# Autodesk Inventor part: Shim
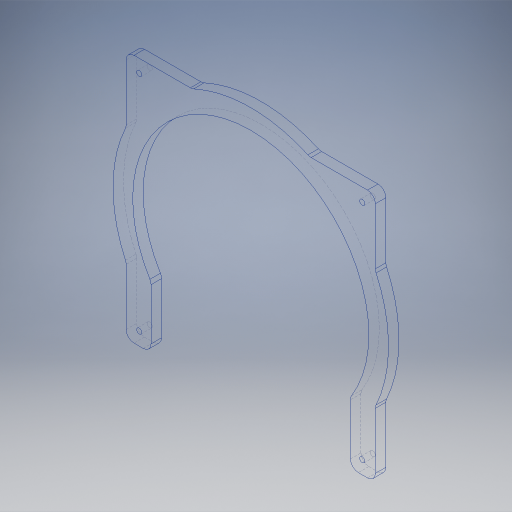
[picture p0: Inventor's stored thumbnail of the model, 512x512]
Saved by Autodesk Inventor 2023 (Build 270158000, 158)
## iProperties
Created: 2024-01
Part Number: Shim
Material: Aluminum 6061
Document SubType Name: Modeling
Designer: tornqvih
Density: 2.7 g/cm^3
Appearance: Aluminum - Flat
Mass: 32.8451 g
Surface Area: 76.8924 cm^2
Volume: 12.1649 cm^3
Author: tornqvih
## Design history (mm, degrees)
sketch "Sketch1"
  geometry: L1 (-47.5, -47.5)-(47.5, -47.5); L2 (47.5, -47.5)-(47.5, 47.5); L3 (47.5, 47.5)-(-47.5, 47.5); L4 (-47.5, 47.5)-(-47.5, -47.5); L5 (-47.5, -47.5)-(47.5, 47.5); L6 (47.5, -47.5)-(-47.5, 47.5); L7 (0, -73.5)-(0, 73.5) reference; C1 r 45 at (0, 0); C2 r 52.5 at (0, 0); 9 further points
  constraints: 12 end point, 2 centre point, 2 coincident, 2 midpoint, 2 parallel, 1 horizontal, 1 perpendicular
  dimensions: "d1" = 90 diameter of C1; "d2" = 95 distance of L2.end L3.end; "d3" = 95 distance of L3.end L1.start; "d19" = 105 diameter of C2
extrude "Extrusion1" new body sketch "Sketch1" distance "d4" = 4; taper "d5" = 0 deg
sketch "Sketch3"
  geometry: L1 (-47.5, -47.5)-(47.5, -47.5) reference; L2 (-38, 0)-(38, 0); L3 (38, 0)-(38, -47.5); L4 (38, -47.5)-(-38, -47.5); L5 (-38, -47.5)-(-38, 0); L6 (-38, 0)-(38, -47.5); L7 (38, 0)-(-38, -47.5); L8 (0, -67.5)-(0, 72.5) reference; L9 (-73.5, 0)-(73.5, 0) reference; 3 further points
  constraints: 12 end point, 3 point on line, 2 midpoint, 2 parallel, 1 horizontal, 1 perpendicular
  dimensions: "d15" = 76 distance of L2.start L2.end
extrude "Extrusion2" cut sketch "Sketch3" extent not by distance; stored distance "d17" = 0; taper "d18" = 0 deg
sketch "Sketch2"
  geometry: L1 (0, -67.5)-(0, 72.5) reference; L2 (-73.5, 0)-(73.5, 0) reference; 5 further points
  constraints: 3 symmetric about line
  dimensions: "d6" = 85 distance of point (42.5, 42.5) point (-42.5, 42.5); "d7" = 85 distance of point (-42.5, -42.5) point (-42.5, 42.5)
hole "Hole1" sketch "Sketch2" at (-42.5, 42.5), (42.5, 42.5), (42.5, -42.5), (-42.5, -42.5) diameter "d8" = 2; stored, may be unused: countersink angle "d12" = 90 deg, drill point angle "d14" = 118 deg; dims "d9" = 6, "d10" = 4, "d11" = 2, "d13" = 8
fillet "Fillet1" dims "d20" = 3
body "Solid1"
